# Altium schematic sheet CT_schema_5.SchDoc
size 372 x 243 mm
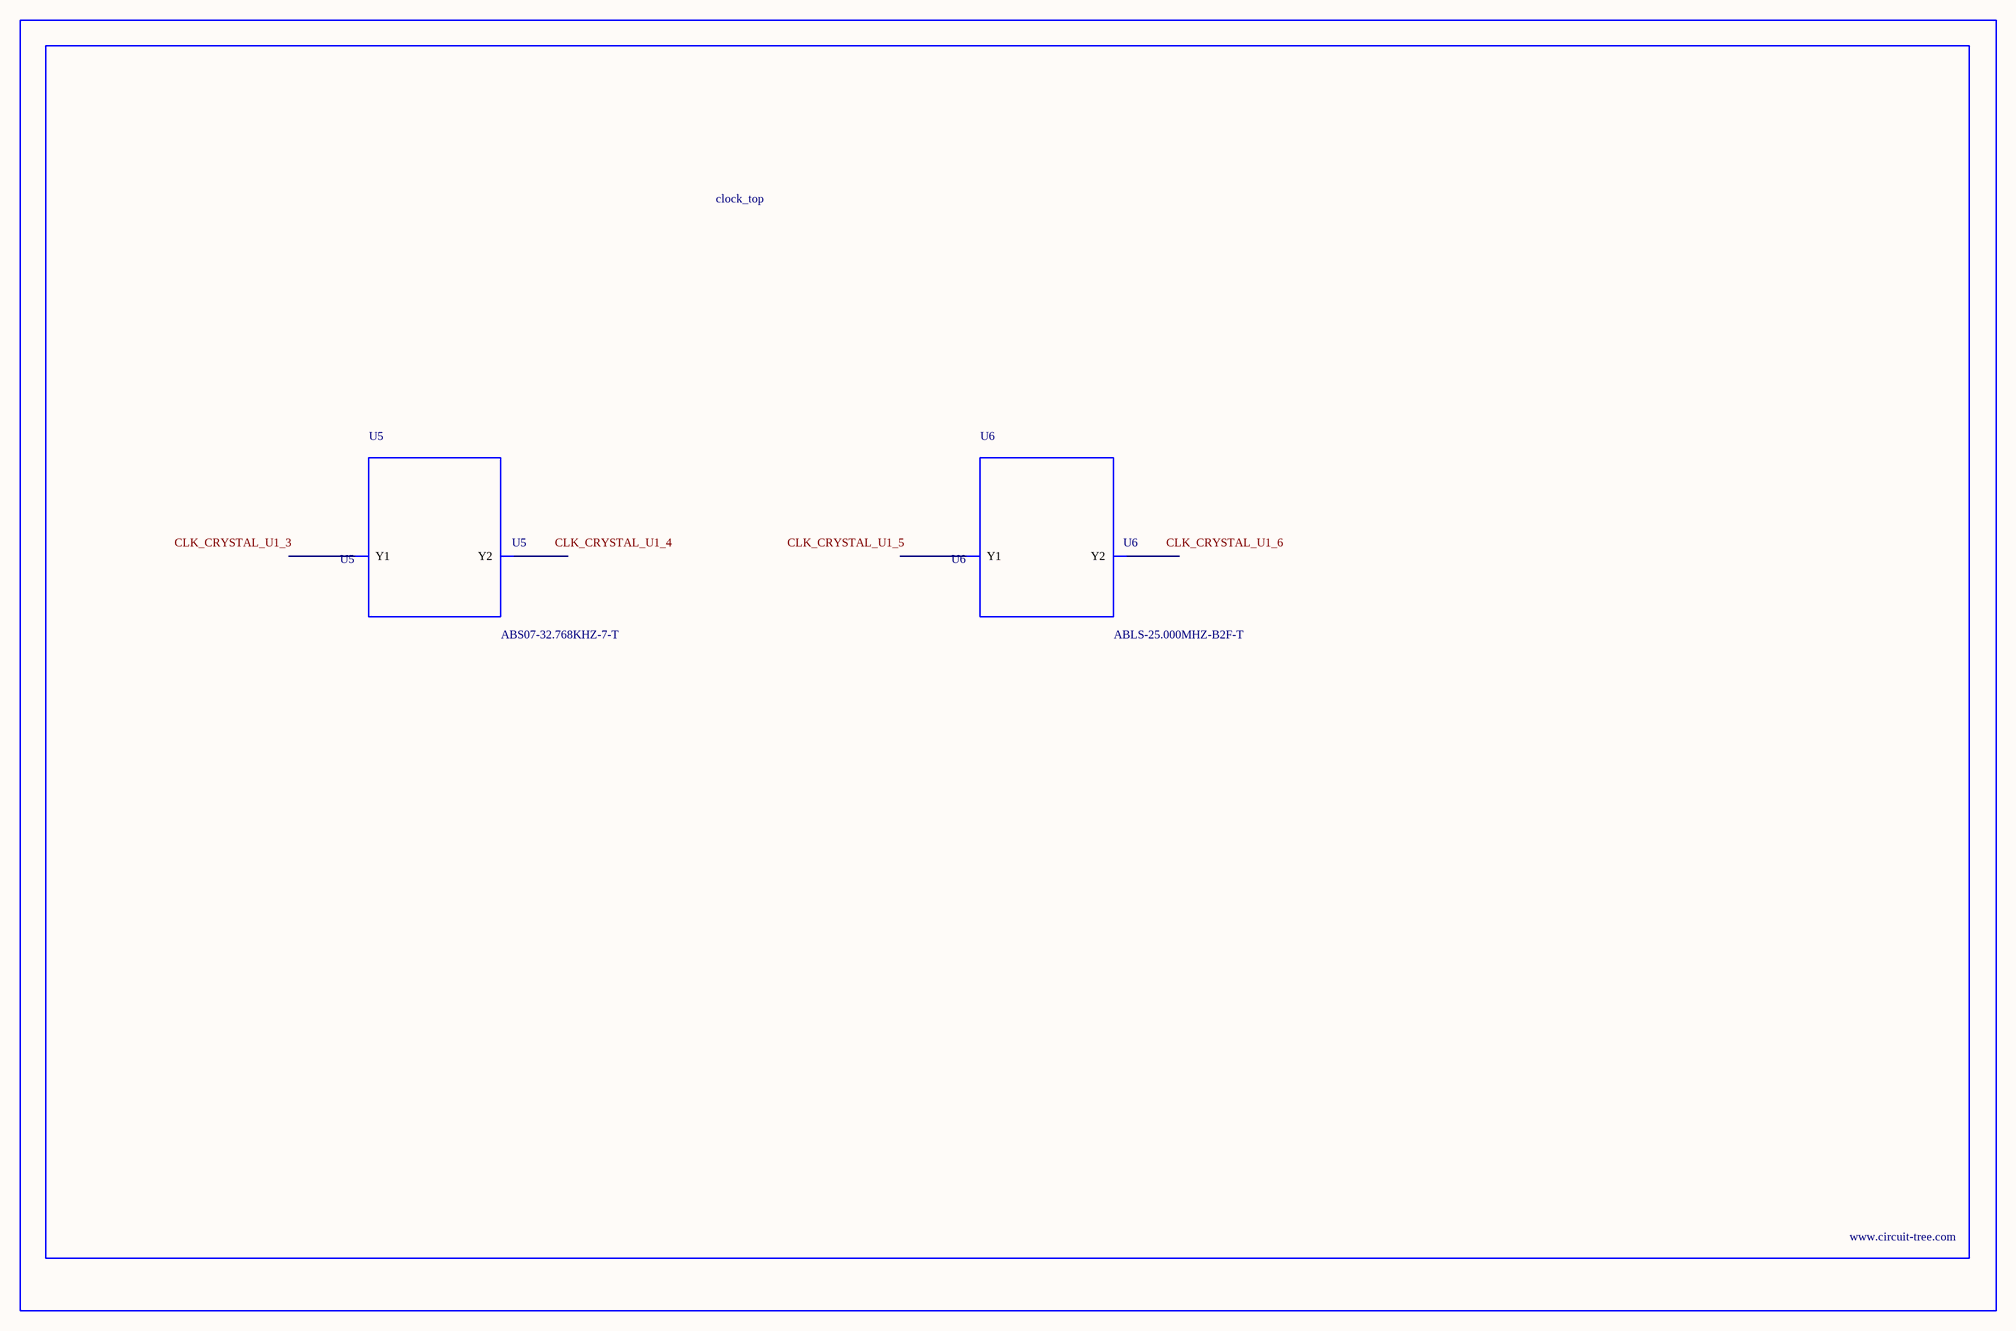
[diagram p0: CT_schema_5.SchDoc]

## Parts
BORDER4  (no value)
U5  ABS07-32.768KHZ-7-T  [ABS07-32.768KHZ-7-T]
U6  ABLS-25.000MHZ-B2F-T  [ABLS-25.000MHZ-B2F-T]

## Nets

Not connected (* = marked no-connect by the designer): U5 1(Y1) 2(Y2); U6 1(Y1) 2(Y2)

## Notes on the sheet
- Labels drawn without touching a wire or pin: CLK_CRYSTAL_U1_3, CLK_CRYSTAL_U1_4, CLK_CRYSTAL_U1_5, CLK_CRYSTAL_U1_6

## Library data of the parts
BORDER4 = BORDER_PAGE4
